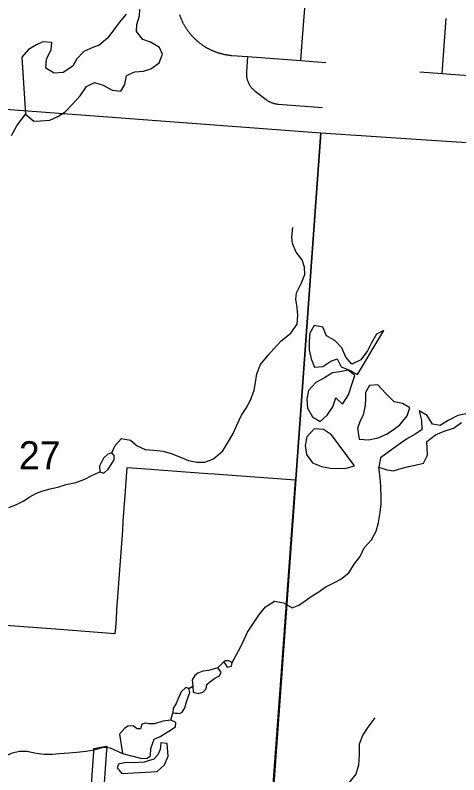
# Model space of a CAD drawing. Extents: x 0 to 34, y 0 to 22.
# Drawn here: x 5.797 to 6.46, y 16.096 to 17.23 of the extents above; entities that cross this region are included whole.
import ezdxf

# ---------------------------------------------------------------- set-up
doc = ezdxf.new("R2010")
doc.units = 0
for name, color, linetype in [('GM_X_Corporation', 7, 'Continuous'), ('GM_X_Minor_Lake', 7, 'Continuous'), ('GM_X_Minor_River', 7, 'Continuous'), ('GM_X_Section_Text', 7, 'Continuous'), ('GM_X_Township_Road', 7, 'Continuous')]:
    doc.layers.add(name, color=color, linetype=linetype)

msp = doc.modelspace()

# ---------------------------------------------------------------- linework, layer by layer
at = {"layer": 'GM_X_Corporation'}
for points in [[(5.7559, 17.0921), (6.2535, 17.0548), (6.1806, 16.0412), (5.682, 16.08)], [(6.2535, 17.0548), (6.7642, 17.0207), (6.6929, 16.0021), (6.1806, 16.0412)]]:
    msp.add_lwpolyline(points, close=True, dxfattribs=at)
for points in [[(6.1826, 16.082), (6.1929, 16.2236), (6.2157, 16.536), (6.0943, 16.545), (6.0848, 16.5457), (6.0584, 16.5477), (6.0452, 16.5487), (6.0319, 16.5497), (6.0187, 16.5507), (6.0055, 16.5516), (6.0002, 16.552), (5.9923, 16.5526), (5.9791, 16.5536), (5.9639, 16.5547), (5.962, 16.528), (5.9614, 16.5186), (5.9601, 16.5012), (5.9592, 16.488), (5.9582, 16.4748), (5.9573, 16.4615), (5.9563, 16.4483), (5.9554, 16.4351), (5.9544, 16.4219), (5.9535, 16.4086), (5.9525, 16.3954), (5.9516, 16.3822), (5.9506, 16.369), (5.9497, 16.3557), (5.9487, 16.3425), (5.9478, 16.3293), (5.9468, 16.3161), (5.9462, 16.3069), (5.8573, 16.3135), (5.7008, 16.3251)], [(5.91, 16.0676), (5.914, 16.1242), (5.9144, 16.1294), (5.9148, 16.1355), (5.9342, 16.139), (5.9333, 16.1266), (5.9292, 16.07)]]:
    msp.add_lwpolyline(points, dxfattribs=at)
at = {"layer": 'GM_X_Minor_Lake'}
for points in [[(5.8125, 17.0824), (5.8249, 17.072), (5.8348, 17.0723), (5.8488, 17.0733), (5.861, 17.0789), (5.8717, 17.086), (5.8835, 17.098), (5.8943, 17.11), (5.9035, 17.124), (5.9157, 17.1299), (5.9285, 17.126), (5.9421, 17.1183), (5.9549, 17.117), (5.9611, 17.1268), (5.9635, 17.1401), (5.9757, 17.1456), (5.9886, 17.1466), (6, 17.1499), (6.0122, 17.1593), (6.0173, 17.1721), (6.0129, 17.1821), (5.9993, 17.1902), (5.9876, 17.1937), (5.9783, 17.206), (5.9787, 17.2162), (5.9831, 17.2294), (5.9835, 17.2393)], [(5.963, 17.2319), (5.9526, 17.2195), (5.943, 17.2063), (5.9353, 17.1958), (5.9227, 17.1857), (5.9132, 17.182), (5.8995, 17.176), (5.8892, 17.1651), (5.8834, 17.1542), (5.8689, 17.1448), (5.8556, 17.1435), (5.8428, 17.1512), (5.8441, 17.1648), (5.8511, 17.1792), (5.8519, 17.1894), (5.8387, 17.1907), (5.8292, 17.1859), (5.817, 17.1788), (5.807, 17.1675)], [(5.807, 17.1675), (5.8125, 17.0824)], [(6.3477, 16.7595), (6.3367, 16.754), (6.3293, 16.7411), (6.3235, 16.729), (6.3135, 16.7159), (6.3002, 16.7095), (6.2912, 16.7199), (6.2853, 16.7336), (6.2744, 16.7444), (6.262, 16.7517), (6.2565, 16.7643), (6.2436, 16.7671), (6.2371, 16.7554), (6.2365, 16.7432), (6.2364, 16.7307), (6.2393, 16.7174), (6.2441, 16.7048), (6.2566, 16.7058), (6.2688, 16.7137), (6.2783, 16.7174), (6.2839, 16.7052), (6.2963, 16.7001), (6.3087, 16.6939)], [(6.3087, 16.6939), (6.3477, 16.7595)], [(6.3003, 16.6803), (6.3046, 16.6924), (6.2944, 16.7005), (6.2819, 16.698), (6.2713, 16.6966), (6.2591, 16.6891), (6.2461, 16.682), (6.2354, 16.67), (6.2326, 16.6571), (6.234, 16.6438), (6.2414, 16.6308), (6.2527, 16.6235), (6.2634, 16.6333), (6.2715, 16.6457), (6.2762, 16.6589), (6.2859, 16.6497), (6.2948, 16.6633)], [(6.2948, 16.6633), (6.3003, 16.6803)], [(6.3111, 16.5975), (6.3247, 16.5962), (6.3392, 16.5991), (6.3517, 16.6046), (6.3616, 16.6114), (6.3716, 16.6189), (6.3827, 16.6324), (6.3866, 16.6441), (6.3757, 16.6507), (6.3632, 16.6531), (6.3509, 16.6654), (6.3389, 16.6784), (6.3264, 16.6774), (6.3202, 16.6672), (6.3205, 16.6577), (6.32, 16.6482), (6.3168, 16.6338), (6.3125, 16.624), (6.3086, 16.6138)], [(6.4702, 16.6353), (6.4585, 16.6328), (6.444, 16.6253), (6.4318, 16.6175), (6.4205, 16.6199), (6.4126, 16.6328), (6.4006, 16.6394), (6.4042, 16.6257), (6.4048, 16.6113), (6.3945, 16.6046), (6.3816, 16.5975), (6.3682, 16.5878), (6.3556, 16.5788), (6.343, 16.5694), (6.3402, 16.5554)], [(6.2695, 16.6036), (6.2575, 16.6117), (6.2438, 16.6126), (6.2327, 16.6006), (6.2303, 16.5877), (6.2325, 16.5744), (6.2414, 16.5618), (6.2546, 16.5563), (6.2682, 16.5539), (6.2784, 16.5538), (6.2917, 16.554), (6.3042, 16.5573)], [(6.3086, 16.6138), (6.3111, 16.5975)], [(6.3523, 16.5515), (6.3621, 16.5503), (6.3754, 16.5539), (6.3849, 16.5565), (6.3944, 16.5583), (6.4069, 16.5616), (6.4128, 16.5733), (6.4118, 16.5938), (6.4248, 16.6039), (6.4378, 16.6091), (6.4518, 16.6138), (6.464, 16.6224)], [(6.3042, 16.5573), (6.2695, 16.6036)], [(5.9416, 16.577), (5.9355, 16.5748), (5.9293, 16.5692), (5.9232, 16.5571), (5.9234, 16.5487), (5.9295, 16.5464), (5.936, 16.5528), (5.9406, 16.5596), (5.9452, 16.5664), (5.9449, 16.5728)], [(5.9449, 16.5728), (5.9416, 16.577)], [(6.3402, 16.5554), (6.3523, 16.5515)], [(6.1139, 16.2572), (6.1203, 16.2586), (6.1211, 16.2639), (6.1163, 16.2666), (6.1113, 16.2663), (6.109, 16.2648)], [(6.109, 16.2648), (6.1139, 16.2572)], [(6.0624, 16.2285), (6.0631, 16.2198), (6.0706, 16.2178), (6.0775, 16.2196), (6.0825, 16.2249), (6.0833, 16.2313), (6.0875, 16.2347), (6.0955, 16.2407), (6.1024, 16.244), (6.1047, 16.2493), (6.0998, 16.2558), (6.0858, 16.2522), (6.0774, 16.2511), (6.0702, 16.2481), (6.0653, 16.2448), (6.0614, 16.238)], [(6.0614, 16.238), (6.0624, 16.2285)], [(6.0396, 16.1881), (6.0427, 16.1877), (6.0465, 16.1899), (6.0507, 16.1964), (6.0531, 16.2051), (6.0554, 16.2122), (6.0578, 16.2191), (6.0567, 16.2251), (6.0522, 16.2267), (6.0453, 16.2203), (6.0402, 16.2086), (6.0375, 16.2029), (6.0329, 16.1958), (6.0328, 16.189)], [(6.0328, 16.189), (6.0357, 16.1885), (6.0396, 16.1881)], [(5.9576, 16.1283), (5.9863, 16.1207), (5.9942, 16.121), (5.9992, 16.1244), (5.9997, 16.1354), (6.0048, 16.1494), (6.0135, 16.1535), (6.0265, 16.1617), (6.0364, 16.1677), (6.0372, 16.1745), (6.0297, 16.178), (6.0175, 16.1762), (6.0054, 16.1725), (5.997, 16.1726), (5.9918, 16.1734), (5.9864, 16.172), (5.9845, 16.1648), (5.9795, 16.1648), (5.9732, 16.1695), (5.9656, 16.1688), (5.9606, 16.1654), (5.9529, 16.1571)], [(5.9529, 16.1571), (5.9576, 16.1283)], [(5.9565, 16.0983), (6.0092, 16.1011), (6.0203, 16.1113), (6.0257, 16.1241), (6.0244, 16.1431), (6.0149, 16.144), (6.0137, 16.1341), (6.0102, 16.1262), (6.0041, 16.1198), (5.99, 16.115), (5.9744, 16.114), (5.9623, 16.1149), (5.9513, 16.1124), (5.9494, 16.1067)], [(5.9494, 16.1067), (5.9565, 16.0983)]]:
    msp.add_lwpolyline(points, dxfattribs=at)
at = {"layer": 'GM_X_Minor_River'}
for points in [[(5.7917, 17.0507), (5.7995, 17.0651), (5.8125, 17.0824)], [(5.9416, 16.577), (5.9465, 16.5881), (5.9562, 16.5981), (5.9694, 16.5957), (5.9792, 16.5876), (5.9912, 16.5818), (6.0045, 16.5809), (6.0181, 16.5796), (6.0302, 16.5761), (6.0441, 16.5703), (6.0562, 16.5656), (6.0687, 16.5632), (6.0804, 16.5631), (6.0934, 16.5679), (6.1071, 16.5799), (6.1175, 16.5961), (6.1226, 16.6059), (6.1284, 16.6183), (6.1354, 16.6331), (6.1423, 16.6436), (6.1489, 16.6557), (6.1539, 16.6705), (6.1564, 16.6849), (6.158, 16.6951), (6.1638, 16.7087), (6.175, 16.7226), (6.1834, 16.7324), (6.1945, 16.744), (6.209, 16.7557), (6.2186, 16.7688), (6.2195, 16.7821), (6.2182, 16.7943), (6.2164, 16.8057), (6.2173, 16.8159), (6.2246, 16.8307), (6.2297, 16.8431), (6.2294, 16.8541), (6.2257, 16.8648), (6.2171, 16.8767), (6.2112, 16.8896), (6.2106, 16.8991), (6.2119, 16.9131)], [(6.1211, 16.2639), (6.1335, 16.287), (6.1393, 16.2983), (6.144, 16.3092), (6.1521, 16.3213), (6.1609, 16.3345), (6.1713, 16.3473), (6.1843, 16.3555), (6.1979, 16.3531), (6.211, 16.3457), (6.2206, 16.3494), (6.2301, 16.3562), (6.2408, 16.3633), (6.2507, 16.3696), (6.2602, 16.3763), (6.274, 16.3834), (6.2835, 16.3886), (6.2957, 16.398), (6.3034, 16.4108), (6.3123, 16.4221), (6.3185, 16.4349), (6.3292, 16.447), (6.3362, 16.4602), (6.3397, 16.4727), (6.3421, 16.4878), (6.3438, 16.5007), (6.3439, 16.5129), (6.3433, 16.525), (6.343, 16.5345), (6.3402, 16.5554)], [(5.7876, 16.4951), (5.799, 16.4996), (5.8089, 16.5048), (5.8189, 16.5111), (5.8288, 16.5167), (5.8387, 16.52), (5.8493, 16.523), (5.8611, 16.5259), (5.8732, 16.5295), (5.8877, 16.5328), (5.901, 16.5376), (5.9105, 16.5428), (5.9234, 16.5487)], [(6.0998, 16.2558), (6.109, 16.2648)], [(6.0567, 16.2251), (6.0624, 16.2285)], [(6.0297, 16.178), (6.0328, 16.189)], [(6.3343, 16.1813), (6.3239, 16.1673), (6.3162, 16.156), (6.3108, 16.142), (6.311, 16.1265), (6.31, 16.1105), (6.3061, 16.0973), (6.295, 16.0838)], [(5.7314, 16.0942), (5.7436, 16.0997), (5.7566, 16.1087), (5.7673, 16.1154), (5.7802, 16.1236), (5.7932, 16.1292), (5.8034, 16.1318), (5.8148, 16.1316), (5.8284, 16.1285), (5.8405, 16.1272), (5.8526, 16.1271), (5.8636, 16.1281), (5.8773, 16.1291), (5.8894, 16.1301), (5.9027, 16.1315), (5.9152, 16.1336), (5.9292, 16.1377), (5.9388, 16.1368), (5.9576, 16.1283)]]:
    msp.add_lwpolyline(points, dxfattribs=at)
at = {"layer": 'GM_X_Township_Road'}
for p, q in [((6.4347, 17.1431), (6.4408, 17.2253)), ((6.2236, 17.1624), (6.2257, 17.1898))]:
    msp.add_line(p, q, dxfattribs=at)
for points in [[(6.2257, 17.1898), (6.2296, 17.2408), (6.2351, 17.3137), (6.2373, 17.3431)], [(6.0426, 17.231), (6.0429, 17.2301), (6.0432, 17.2292), (6.0436, 17.2283), (6.0439, 17.2274), (6.0442, 17.2266), (6.0446, 17.2257), (6.045, 17.2248), (6.0453, 17.2239), (6.0457, 17.2231), (6.0461, 17.2222), (6.0465, 17.2213), (6.0469, 17.2205), (6.0473, 17.2196), (6.0478, 17.2188), (6.0482, 17.218), (6.0486, 17.2171), (6.0491, 17.2163), (6.0496, 17.2155), (6.05, 17.2146), (6.0505, 17.2138), (6.051, 17.213), (6.0515, 17.2122), (6.052, 17.2114), (6.0525, 17.2106), (6.053, 17.2098), (6.0536, 17.209), (6.0541, 17.2083), (6.0547, 17.2075), (6.0552, 17.2067), (6.0558, 17.206), (6.0564, 17.2052), (6.0569, 17.2045), (6.0575, 17.2037), (6.0581, 17.203), (6.0587, 17.2023), (6.0593, 17.2015), (6.0599, 17.2008), (6.0606, 17.2001), (6.0612, 17.1994), (6.0618, 17.1987), (6.0625, 17.198), (6.0631, 17.1973), (6.0638, 17.1966), (6.0645, 17.196), (6.0652, 17.1953), (6.0658, 17.1947), (6.0665, 17.194), (6.0672, 17.1934), (6.0679, 17.1927), (6.0686, 17.1921), (6.0694, 17.1915), (6.0701, 17.1909), (6.0708, 17.1903), (6.0715, 17.1897), (6.0723, 17.1891), (6.073, 17.1885), (6.0738, 17.1879), (6.0745, 17.1874), (6.0753, 17.1868), (6.0761, 17.1863), (6.0769, 17.1857), (6.0776, 17.1852), (6.0784, 17.1847), (6.0792, 17.1842), (6.08, 17.1836), (6.0808, 17.1831), (6.0816, 17.1827), (6.0825, 17.1822), (6.0833, 17.1817), (6.0841, 17.1812), (6.0849, 17.1808), (6.0858, 17.1803), (6.0866, 17.1799), (6.0875, 17.1795), (6.0883, 17.179), (6.0892, 17.1786), (6.09, 17.1782), (6.0909, 17.1778), (6.0917, 17.1775), (6.0926, 17.1771), (6.0935, 17.1767), (6.0944, 17.1764), (6.0952, 17.176), (6.0961, 17.1757), (6.097, 17.1753), (6.0979, 17.175), (6.0988, 17.1747), (6.0997, 17.1744), (6.1006, 17.1741), (6.1015, 17.1738), (6.1024, 17.1736), (6.1033, 17.1733), (6.1042, 17.1731), (6.1052, 17.1728), (6.1061, 17.1726), (6.107, 17.1724), (6.1079, 17.1721), (6.1088, 17.1719), (6.1098, 17.1717), (6.1107, 17.1716), (6.1116, 17.1714), (6.1126, 17.1712), (6.1135, 17.1711), (6.1144, 17.1709), (6.1154, 17.1708), (6.1163, 17.1707), (6.1172, 17.1705), (6.1182, 17.1704), (6.1191, 17.1703), (6.1201, 17.1702), (6.121, 17.1702), (6.1443, 17.1684), (6.2236, 17.1624), (6.2614, 17.1595)], [(6.1443, 17.1684), (6.1426, 17.1457), (6.1425, 17.1443), (6.1425, 17.1434), (6.1425, 17.1424), (6.1426, 17.1411), (6.1427, 17.1401), (6.1428, 17.1392), (6.1429, 17.1382), (6.143, 17.1373), (6.1432, 17.1364), (6.1434, 17.1355), (6.1437, 17.1345), (6.1439, 17.1336), (6.1442, 17.1327), (6.1445, 17.1318), (6.1449, 17.131), (6.1452, 17.1301), (6.1456, 17.1292), (6.146, 17.1284), (6.1465, 17.1275), (6.1469, 17.1267), (6.1474, 17.1259), (6.1479, 17.1251), (6.1484, 17.1243), (6.149, 17.1235), (6.1496, 17.1228), (6.1502, 17.122), (6.1508, 17.1213), (6.1514, 17.1206), (6.1521, 17.1199), (6.1527, 17.1193), (6.1534, 17.1186), (6.1541, 17.118), (6.1549, 17.1174), (6.1556, 17.1168), (6.1723, 17.1042), (6.1731, 17.1036), (6.1739, 17.103), (6.1746, 17.1025), (6.1755, 17.102), (6.1763, 17.1016), (6.1771, 17.1011), (6.178, 17.1007), (6.1788, 17.1003), (6.1797, 17.0999), (6.1806, 17.0996), (6.1815, 17.0993), (6.1824, 17.099), (6.1833, 17.0987), (6.1842, 17.0984), (6.1851, 17.0982), (6.186, 17.098), (6.187, 17.0979), (6.1879, 17.0977), (6.1888, 17.0976), (6.1898, 17.0975), (6.2563, 17.0925)], [(6.4017, 17.1455), (6.4347, 17.1431), (6.5137, 17.1373)]]:
    msp.add_lwpolyline(points, dxfattribs=at)

# ---------------------------------------------------------------- texts
at = {"layer": 'GM_X_Section_Text'}
msp.add_text('27', height=0.04186, rotation=0, dxfattribs=at).set_placement((5.8027, 16.5524))

doc.saveas('drawing.dxf')
